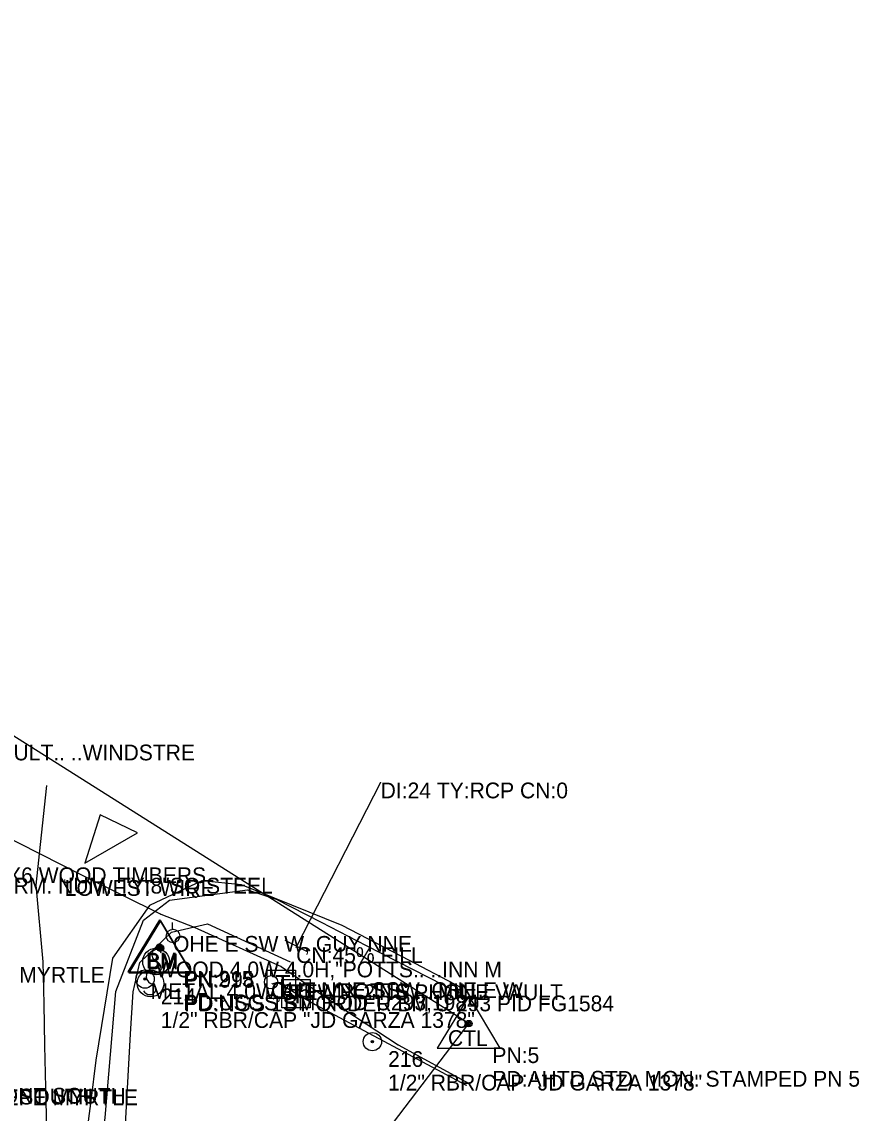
# Model space of a CAD drawing. Extents: x 997398 to 1003416, y 334596 to 337085.
# Drawn here: x 999595.3 to 999861, y 336485.6 to 336831.9 of the extents above; entities that cross this region are included whole.
import ezdxf

# ---------------------------------------------------------------- set-up
doc = ezdxf.new("R2010")
doc.units = 0
for name, color, linetype in [('Default', 7, 'Continuous'), ('S_DITCHLINE', 7, 'Continuous'), ('S_DRG_PT_SYM', 7, 'Continuous'), ('S_EDGE_CONCRETE', 7, 'Continuous'), ('S_EDGE_PAVEMENT', 7, 'Continuous'), ('S_ELECTRIC_UTILITIES_ANNOT', 7, 'Continuous'), ('S_FIBER_OPTIC_CABLE', 7, 'Continuous'), ('S_FIBER_OPTIC_CABLE_ANNOT', 7, 'Continuous'), ('S_GAS_UTILITIES_ANNOT', 7, 'Continuous'), ('S_GRD_PT_SYM', 7, 'Continuous'), ('S_HEADWALL', 7, 'Continuous'), ('S_IRON_PIN', 7, 'Continuous'), ('S_IRON_PIN_ANNOT', 7, 'Continuous'), ('S_LANDSCAPING_ANNOT', 7, 'Continuous'), ('S_PAVEMENT_CROWN', 7, 'Continuous'), ('S_PRIMARY_CTL', 7, 'Continuous'), ('S_PRIMARY_CTL_ANNOT', 7, 'Continuous'), ('S_SHOULDER', 7, 'Continuous'), ('S_SIDE_DRAIN', 7, 'Continuous'), ('S_SIDE_DRAIN_ANNOT', 7, 'Continuous'), ('S_SIGN', 7, 'Continuous'), ('S_SIGN_ANNOT', 7, 'Continuous'), ('S_TELEPHONE_UTILITIES', 7, 'Continuous'), ('S_TELEPHONE_UTILITIES_ANNOT', 7, 'Continuous'), ('S_TREE_ANNOT', 7, 'Continuous'), ('S_UTILITY_POLE', 7, 'Continuous'), ('S_UTILITY_POLE_ANNOT', 7, 'Continuous'), ('S_UTL_PT_SYM', 7, 'Continuous')]:
    doc.layers.add(name, color=color, linetype=linetype)

msp = doc.modelspace()

# ---------------------------------------------------------------- linework, layer by layer
at = {"layer": 'Default'}
for p, q in [((999737.12, 336514.03), (999233.93, 336831.87)), ((999557.02, 336277.74), (999737.12, 336514.03))]:
    msp.add_line(p, q, dxfattribs=at)
at = {"layer": 'S_DITCHLINE'}
msp.add_lwpolyline([(999585.56, 336336.15), (999591.87, 336353.69), (999598.19, 336371.23), (999604.53, 336388.73), (999609.68, 336403.37), (999615.75, 336417.57), (999621.81, 336431.76), (999624.66, 336451.18), (999627.5, 336470.6), (999628.27, 336483.98), (999629.05, 336497.37), (999629.83, 336510.76), (999630.6, 336524.14), (999632.81, 336533.43), (999642.82, 336543.03), (999654.22, 336545.64), (999667.32, 336539.63), (999680.41, 336533.63)], dxfattribs=at)
at = {"layer": 'S_DRG_PT_SYM'}
for points in [[(999709.16, 336590.51), (999709.16, 336590.56), (999709.16, 336590.51), (999709.11, 336590.51), (999709.16, 336590.51), (999709.16, 336590.46), (999709.16, 336590.51), (999709.21, 336590.51)], [(999682.36, 336538.28), (999682.36, 336538.33), (999682.36, 336538.28), (999682.31, 336538.28), (999682.36, 336538.28), (999682.36, 336538.23), (999682.36, 336538.28), (999682.41, 336538.28)]]:
    msp.add_lwpolyline(points, dxfattribs=at)
at = {"layer": 'S_EDGE_CONCRETE'}
for points in [[(999615.31, 336564.95), (999631.99, 336574.59), (999620.13, 336580.25)], [(999620.13, 336580.25), (999615.31, 336564.95)]]:
    msp.add_lwpolyline(points, dxfattribs=at)
at = {"layer": 'S_EDGE_PAVEMENT'}
msp.add_lwpolyline([(999734.82, 336525.42), (999715.9, 336535.28), (999696.99, 336545.14), (999681.02, 336551.61), (999665.04, 336558.07), (999652.4, 336559.35), (999635.86, 336551.49), (999624.04, 336534.77), (999621.42, 336518.62), (999618.81, 336502.47), (999617.17, 336489.53), (999615.52, 336476.58), (999613.88, 336463.64), (999612.24, 336450.69), (999611.51, 336445.87)], dxfattribs=at)
at = {"layer": 'S_FIBER_OPTIC_CABLE'}
for p, q in [((999584.26, 336576.46), (999614.5, 336561.11)), ((999614.5, 336561.11), (999639.41, 336548.74)), ((999639.41, 336548.74), (999649.95, 336544.62)), ((999649.95, 336544.62), (999677.57, 336532.15)), ((999677.57, 336532.15), (999690.74, 336523.04)), ((999674.75, 336526.69), (999676.44, 336527.14)), ((999676.44, 336527.14), (999680.47, 336524.71)), ((999680.47, 336524.71), (999688.4, 336520.09)), ((999690.74, 336523.04), (999714.7, 336507.27)), ((999688.4, 336520.09), (999736.25, 336494.47)), ((999714.7, 336507.27), (999737.3, 336495.01))]:
    msp.add_line(p, q, dxfattribs=at)
at = {"layer": 'S_GRD_PT_SYM'}
msp.add_lwpolyline([(999608.93, 336559.57), (999608.93, 336559.62), (999608.93, 336559.57), (999608.88, 336559.57), (999608.93, 336559.57), (999608.93, 336559.52), (999608.93, 336559.57), (999608.98, 336559.57)], dxfattribs=at)
at = {"layer": 'S_HEADWALL'}
msp.add_lwpolyline([(999686, 336536.81), (999678.89, 336540.35)], dxfattribs=at)
at = {"layer": 'S_IRON_PIN'}
for centre, radius in [((999634.41, 336528.18), 2.91), ((999634.41, 336528.18), 0.411), ((999634.41, 336528.18), 0.262), ((999634.41, 336528.18), 0.212), ((999634.41, 336528.18), 0.145), ((999634.41, 336528.18), 0.0822), ((999634.41, 336528.18), 0.0581), ((999706.53, 336508.31), 2.91), ((999706.53, 336508.31), 0.411), ((999706.53, 336508.31), 0.262), ((999706.53, 336508.31), 0.212), ((999706.53, 336508.31), 0.145), ((999706.53, 336508.31), 0.0822), ((999706.53, 336508.31), 0.0581)]:
    msp.add_circle(centre, radius, dxfattribs=at)
at = {"layer": 'S_PAVEMENT_CROWN'}
msp.add_lwpolyline([(999603.2, 336480.51), (999602.93, 336493.78), (999602.67, 336507.05), (999602.4, 336520.33), (999602.13, 336533.6), (999599.82, 336557.94), (999601.51, 336573.77), (999603.2, 336589.59)], dxfattribs=at)
at = {"layer": 'S_PRIMARY_CTL'}
for p, q in [((999639.02, 336546.95), (999628.99, 336530.43)), ((999639.35, 336546.64), (999629.32, 336530.13)), ((999639.02, 336546.95), (999648.85, 336530.43)), ((999639.35, 336546.64), (999649.17, 336530.13)), ((999628.99, 336530.43), (999648.85, 336530.43)), ((999629.32, 336530.13), (999649.17, 336530.13)), ((999737.12, 336522.73), (999727.09, 336506.22)), ((999737.12, 336522.73), (999746.94, 336506.22)), ((999727.09, 336506.22), (999746.94, 336506.22))]:
    msp.add_line(p, q, dxfattribs=at)
for centre, radius in [((999639.02, 336538.25), 1.04), ((999639.35, 336537.94), 1.04), ((999639.02, 336538.25), 0.609), ((999639.02, 336538.25), 0.344), ((999639.35, 336537.94), 0.609), ((999639.35, 336537.94), 0.344), ((999737.12, 336514.03), 1.04), ((999737.12, 336514.03), 0.609), ((999737.12, 336514.03), 0.344)]:
    msp.add_circle(centre, radius, dxfattribs=at)
at = {"layer": 'S_SHOULDER'}
msp.add_lwpolyline([(999597.83, 336392.88), (999602.77, 336406.03), (999607.71, 336419.18), (999612.43, 336427.01), (999617.85, 336448.45), (999619.83, 336466.34), (999621.81, 336484.23), (999623.46, 336504.24), (999625.11, 336524.24), (999633.96, 336546.84), (999642.15, 336553.19), (999666.92, 336556.51), (999675.99, 336553.51), (999690.3, 336546.17), (999704.62, 336538.83), (999719.32, 336531.31), (999734.02, 336523.79)], dxfattribs=at)
at = {"layer": 'S_SIDE_DRAIN'}
msp.add_line((999709.16, 336590.51), (999682.36, 336538.28), dxfattribs=at)
at = {"layer": 'S_SIGN'}
for centre in [(999637.9, 336533.72), (999636.16, 336526.79)]:
    msp.add_circle(centre, 4.24, dxfattribs=at)
for centre, radius, start, end in [((999638.02, 336535.88), 1.62, 16.5258, 156.8957), ((999639.06, 336535.98), 2.55, 167.1196, 241.9813), ((999637.2, 336531.44), 2.38, 358.6529, 73.7063), ((999636.29, 336528.94), 1.62, 16.5258, 156.8957), ((999637.64, 336532.32), 2.17, 204.641, 335.359), ((999637.33, 336529.04), 2.55, 167.1196, 241.9813), ((999635.46, 336524.51), 2.38, 358.6529, 73.7063), ((999635.9, 336525.39), 2.17, 204.641, 335.359)]:
    msp.add_arc(centre, radius, start, end, dxfattribs=at)
at = {"layer": 'S_TELEPHONE_UTILITIES'}
for points in [[(999673.16, 336521.97), (999673.16, 336530.97), (999682.16, 336530.97), (999682.16, 336521.97)], [(999677.8, 336519.01), (999677.8, 336528.01), (999686.8, 336528.01), (999686.8, 336519.01)]]:
    msp.add_lwpolyline(points, close=True, dxfattribs=at)
at = {"layer": 'S_UTILITY_POLE'}
for p, q in [((999643.17, 336543.97), (999643.17, 336546.08)), ((999674.28, 336529.3), (999674.28, 336531.41))]:
    msp.add_line(p, q, dxfattribs=at)
for centre in [(999643.29, 336541.83), (999674.4, 336527.16)]:
    msp.add_circle(centre, 2.13, dxfattribs=at)
at = {"layer": 'S_UTL_PT_SYM'}
for points in [[(999614.5, 336561.11), (999614.5, 336561.16), (999614.5, 336561.11), (999614.45, 336561.11), (999614.5, 336561.11), (999614.5, 336561.06), (999614.5, 336561.11), (999614.55, 336561.11)], [(999608.93, 336559.57), (999608.93, 336559.62), (999608.93, 336559.57), (999608.88, 336559.57), (999608.93, 336559.57), (999608.93, 336559.52), (999608.93, 336559.57), (999608.98, 336559.57)], [(999639.41, 336548.74), (999639.41, 336548.79), (999639.41, 336548.74), (999639.36, 336548.74), (999639.41, 336548.74), (999639.41, 336548.69), (999639.41, 336548.74), (999639.46, 336548.74)], [(999649.95, 336544.62), (999649.95, 336544.67), (999649.95, 336544.62), (999649.9, 336544.62), (999649.95, 336544.62), (999649.95, 336544.57), (999649.95, 336544.62), (999650, 336544.62)], [(999677.57, 336532.15), (999677.57, 336532.2), (999677.57, 336532.15), (999677.52, 336532.15), (999677.57, 336532.15), (999677.57, 336532.1), (999677.57, 336532.15), (999677.62, 336532.15)], [(999674.75, 336526.69), (999674.75, 336526.74), (999674.75, 336526.69), (999674.7, 336526.69), (999674.75, 336526.69), (999674.75, 336526.64), (999674.75, 336526.69), (999674.8, 336526.69)], [(999676.44, 336527.14), (999676.44, 336527.19), (999676.44, 336527.14), (999676.39, 336527.14), (999676.44, 336527.14), (999676.44, 336527.09), (999676.44, 336527.14), (999676.49, 336527.14)], [(999680.47, 336524.71), (999680.47, 336524.76), (999680.47, 336524.71), (999680.42, 336524.71), (999680.47, 336524.71), (999680.47, 336524.66), (999680.47, 336524.71), (999680.52, 336524.71)], [(999690.74, 336523.04), (999690.74, 336523.09), (999690.74, 336523.04), (999690.69, 336523.04), (999690.74, 336523.04), (999690.74, 336522.99), (999690.74, 336523.04), (999690.79, 336523.04)], [(999688.4, 336520.09), (999688.4, 336520.14), (999688.4, 336520.09), (999688.35, 336520.09), (999688.4, 336520.09), (999688.4, 336520.04), (999688.4, 336520.09), (999688.45, 336520.09)], [(999714.7, 336507.27), (999714.7, 336507.32), (999714.7, 336507.27), (999714.65, 336507.27), (999714.7, 336507.27), (999714.7, 336507.22), (999714.7, 336507.27), (999714.75, 336507.27)], [(999736.25, 336494.47), (999736.25, 336494.52), (999736.25, 336494.47), (999736.2, 336494.47), (999736.25, 336494.47), (999736.25, 336494.42), (999736.25, 336494.47), (999736.3, 336494.47)], [(999737.3, 336495.01), (999737.3, 336495.06), (999737.3, 336495.01), (999737.25, 336495.01), (999737.3, 336495.01), (999737.3, 336494.96), (999737.3, 336495.01), (999737.35, 336495.01)]]:
    msp.add_lwpolyline(points, dxfattribs=at)

# ---------------------------------------------------------------- texts
at = {"layer": 'S_ELECTRIC_UTILITIES_ANNOT'}
msp.add_text('LOWEST WIRE', height=5, dxfattribs=at).set_placement((999608.93, 336554.57))
at = {"layer": 'S_FIBER_OPTIC_CABLE_ANNOT'}
msp.add_text('CONT SOUTH', height=5, dxfattribs=at).set_placement((999573.71, 336488.39))
at = {"layer": 'S_GAS_UTILITIES_ANNOT'}
msp.add_text('CONT SOUTH', height=5, dxfattribs=at).set_placement((999584.12, 336488.64))
at = {"layer": 'S_IRON_PIN_ANNOT'}
for s, p in [('214', (999639.41, 336520.18)), ('1/2" RBR/CAP "JD GARZA 1378"', (999639.41, 336512.68)), ('216', (999711.53, 336500.31)), ('1/2" RBR/CAP "JD GARZA 1378"', (999711.53, 336492.81))]:
    msp.add_text(s, height=5, dxfattribs=at).set_placement(p)
at = {"layer": 'S_LANDSCAPING_ANNOT'}
msp.add_text('PLANTER,6X6 WOOD TIMBERS', height=5, dxfattribs=at).set_placement((999554.22, 336558.6))
at = {"layer": 'S_PRIMARY_CTL'}
for s, p in [('BM', (999634.65, 336531.54)), ('BM', (999634.98, 336531.24)), ('CTL', (999730.53, 336506.95))]:
    msp.add_text(s, height=5, rotation=360, dxfattribs=at).set_placement(p)
at = {"layer": 'S_PRIMARY_CTL_ANNOT'}
for s, p in [('PN:215', (999646.52, 336525.75)), ('PN:998', (999646.85, 336525.44)), ('PD:USGS BM ROD"U293,1984"', (999646.52, 336518.25)), ('PD:NGS 1ST ORDER BM U 293 PID FG1584', (999646.85, 336517.94)), ('PN:5', (999744.62, 336501.53)), ('PD:AHTD STD. MON. STAMPED PN 5', (999744.62, 336494.03))]:
    msp.add_text(s, height=5, dxfattribs=at).set_placement(p)
at = {"layer": 'S_SIDE_DRAIN_ANNOT'}
for s, p in [('DI:24 TY:RCP CN:0', (999709.16, 336585.51)), ('CN:45% FILL', (999682.36, 336533.28))]:
    msp.add_text(s, height=5, dxfattribs=at).set_placement(p)
at = {"layer": 'S_SIGN_ANNOT'}
for s, p in [('0 SHELL PERM. NUM. TY:8"SQ STEEL', (999555.17, 336555.29)), ('WOOD,4.0W,4.0H,"POTTS.. ..INN M', (999637.9, 336528.72)), ('METAL,4.0W,4.5H,"POTTS.. ..VILL', (999636.16, 336521.79))]:
    msp.add_text(s, height=5, dxfattribs=at).set_placement(p)
at = {"layer": 'S_TELEPHONE_UTILITIES'}
for p in [(999675.72, 336523.47), (999680.37, 336520.51)]:
    msp.add_text('T', height=6, rotation=360, dxfattribs=at).set_placement(p)
at = {"layer": 'S_TELEPHONE_UTILITIES_ANNOT'}
for s, p in [('4.0NS X2.5EW VAULT.. ..WINDSTRE', (999536.94, 336597.55)), ("3' EW X 2'NS PHONE VAULT", (999677.88, 336521.49))]:
    msp.add_text(s, height=5, dxfattribs=at).set_placement(p)
at = {"layer": 'S_TREE_ANNOT'}
for p in [(999562.18, 336527.02), (999572.71, 336488.15)]:
    msp.add_text('12CREPE MYRTLE', height=5, dxfattribs=at).set_placement(p)
at = {"layer": 'S_UTILITY_POLE_ANNOT'}
for s, p in [('OHE E SW W, GUY NNE', (999643.29, 336536.83)), ('OHT NNE SSW, OHE E W', (999674.4, 336522.16))]:
    msp.add_text(s, height=5, dxfattribs=at).set_placement(p)

doc.saveas('drawing.dxf')
